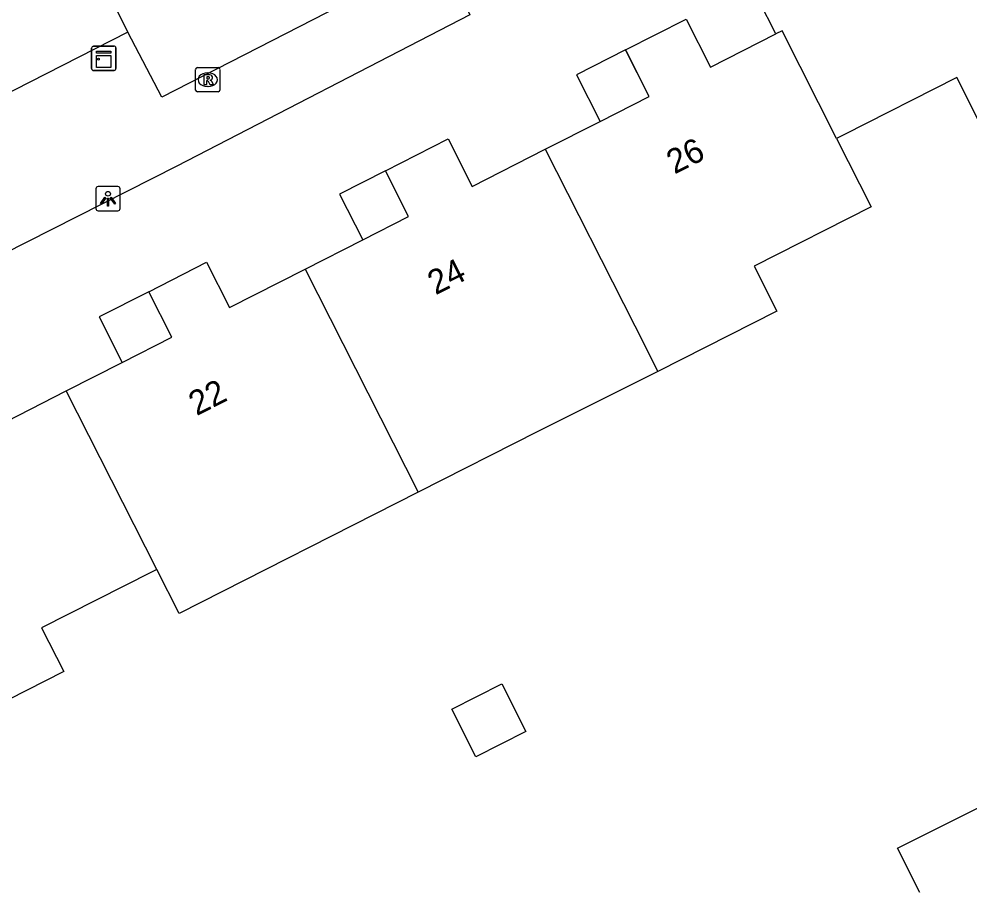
# Model space of a CAD drawing. Extents: x 162722 to 165099, y 384721 to 386283.
# Drawn here: x 163831.42 to 163870.52, y 385039.4 to 385075.21 of the extents above; entities that cross this region are included whole.
import ezdxf

# ---------------------------------------------------------------- set-up
doc = ezdxf.new("R2010")
doc.units = 0
for name, color, linetype in [('IMGEO_Kast', 7, 'Continuous'), ('IMGEO_Lichtpunt', 7, 'Continuous'), ('IMGEO_Pand', 7, 'Continuous'), ('IMGEO_Pand_nummerreeks', 7, 'Continuous'), ('IMGEO_Pand_overbouw', 7, 'Continuous'), ('IMGEO_Parkeervlak_open', 7, 'Continuous'), ('IMGEO_Rioolput', 7, 'Continuous'), ('IMGEO_Voetpad_open', 7, 'Continuous')]:
    doc.layers.add(name, color=color, linetype=linetype)

msp = doc.modelspace()

# ---------------------------------------------------------------- linework, layer by layer
at = {"layer": 'IMGEO_Kast'}
for p, q in [((163834.403, 385073.167), (163834.403, 385074.008)), ((163834.403, 385074.008), (163834.403, 385073.167)), ((163834.478, 385074.092), (163835.319, 385074.092)), ((163835.319, 385074.092), (163834.478, 385074.092)), ((163835.403, 385074.017), (163835.403, 385073.176)), ((163835.403, 385073.176), (163835.403, 385074.017)), ((163835.328, 385073.092), (163834.487, 385073.092)), ((163834.487, 385073.092), (163835.328, 385073.092))]:
    msp.add_line(p, q, dxfattribs=at)
for points in [[(163834.598, 385073.882), (163835.198, 385073.882), (163835.198, 385073.797), (163834.598, 385073.797), (163834.598, 385073.882)], [(163834.598, 385073.707), (163835.198, 385073.707), (163835.198, 385073.218), (163834.598, 385073.218), (163834.598, 385073.707)]]:
    msp.add_lwpolyline(points, dxfattribs=at)
msp.add_circle((163834.682, 385073.556), 0.0377, dxfattribs=at)
for centre, start, end in [((163834.481, 385074.014), 92.4484, 184.2845), ((163834.481, 385074.014), 92.4484, 184.2845), ((163835.325, 385074.014), 2.4484, 94.2845), ((163835.325, 385074.014), 2.4484, 94.2845), ((163834.481, 385073.17), 182.4484, 274.2845), ((163834.481, 385073.17), 182.4484, 274.2845), ((163835.325, 385073.17), 272.4484, 4.2845), ((163835.325, 385073.17), 272.4484, 4.2845)]:
    msp.add_arc(centre, 0.0779, start, end, dxfattribs=at)
at = {"layer": 'IMGEO_Lichtpunt'}
for p, q in [((163834.58, 385068.225), (163834.58, 385067.418)), ((163834.58, 385068.225), (163834.58, 385067.418)), ((163835.482, 385068.32), (163834.674, 385068.32)), ((163835.482, 385068.32), (163834.674, 385068.32)), ((163835.576, 385067.418), (163835.576, 385068.225)), ((163835.576, 385067.418), (163835.576, 385068.225)), ((163834.674, 385067.324), (163835.482, 385067.324)), ((163834.674, 385067.324), (163835.482, 385067.324))]:
    msp.add_line(p, q, dxfattribs=at)
for points in [[(163834.954, 385067.889), (163834.993, 385067.861), (163834.805, 385067.599), (163834.767, 385067.626), (163834.954, 385067.889)], [(163835.056, 385067.841), (163835.103, 385067.841), (163835.103, 385067.519), (163835.056, 385067.519), (163835.056, 385067.841)], [(163835.166, 385067.861), (163835.204, 385067.888), (163835.391, 385067.626), (163835.352, 385067.598), (163835.166, 385067.861)]]:
    msp.add_lwpolyline(points, dxfattribs=at)
msp.add_circle((163835.079, 385068.023), 0.0994, dxfattribs=at)
for centre, start, end in [((163834.674, 385068.225), 90, 180), ((163834.674, 385068.225), 90, 180), ((163835.482, 385068.225), 0, 90), ((163835.482, 385068.225), 0, 90), ((163834.674, 385067.418), 180, 270), ((163834.674, 385067.418), 180, 270), ((163835.482, 385067.418), 270, 0), ((163835.482, 385067.418), 270, 360)]:
    msp.add_arc(centre, 0.0946, start, end, dxfattribs=at)
at = {"layer": 'IMGEO_Pand'}
for points in [[(163862.538, 385074.592), (163861.139, 385077.348), (163864.257, 385078.931), (163863.307, 385080.802), (163865.619, 385081.976), (163866.538, 385080.166), (163868.8, 385081.297), (163871.258, 385082.545)], [(163853.059, 385069.852), (163855.314, 385070.997), (163857.331, 385072.021), (163856.376, 385073.904), (163856.356, 385073.944), (163858.844, 385075.207), (163859.85, 385073.227), (163862.538, 385074.592)], [(163865.034, 385070.295), (163862.792, 385074.721), (163862.538, 385074.592)], [(163875.874, 385073.435), (163870.931, 385070.924), (163869.976, 385072.803), (163865.335, 385070.447), (163865.034, 385070.295)], [(163843.179, 385064.927), (163845.555, 385066.134), (163847.437, 385067.09), (163846.484, 385068.966), (163849.067, 385070.277), (163850.057, 385068.328), (163853.059, 385069.852)], [(163865.034, 385070.295), (163866.457, 385067.487), (163861.641, 385065.042), (163862.579, 385063.193), (163857.691, 385060.711)], [(163853.059, 385069.852), (163856.741, 385062.586), (163857.691, 385060.711)], [(163833.358, 385059.919), (163835.665, 385061.09), (163837.703, 385062.124), (163836.753, 385063.996), (163839.134, 385065.205), (163840.075, 385063.351), (163843.179, 385064.927)], [(163843.179, 385064.927), (163847.83, 385055.75)], [(163857.691, 385060.711), (163852.747, 385058.247), (163847.83, 385055.75)], [(163823.548, 385054.918), (163825.861, 385056.093), (163827.851, 385057.103), (163826.898, 385058.981), (163829.459, 385060.282), (163830.405, 385058.419), (163833.358, 385059.919)], [(163837.08, 385052.574), (163833.358, 385059.919)], [(163847.83, 385055.75), (163838, 385050.758), (163837.08, 385052.574)], [(163837.08, 385052.574), (163836.867, 385052.466), (163832.345, 385050.169), (163833.255, 385048.378), (163829.454, 385046.447)], [(163852.262, 385045.918), (163850.203, 385044.873), (163849.211, 385046.826), (163851.27, 385047.872), (163852.262, 385045.918)], [(163868.454, 385039.298), (163867.535, 385041.115), (163872.606, 385043.657), (163871.554, 385045.755), (163875.979, 385047.973), (163877.043, 385045.849), (163877.48, 385046.068)]]:
    msp.add_lwpolyline(points, dxfattribs=at)
at = {"layer": 'IMGEO_Pand_overbouw'}
for points in [[(163856.356, 385073.944), (163854.339, 385072.919), (163855.314, 385070.997), (163857.331, 385072.021)], [(163846.484, 385068.966), (163844.602, 385068.01), (163845.555, 385066.134), (163847.437, 385067.09)], [(163836.753, 385063.996), (163834.715, 385062.961), (163835.665, 385061.09), (163837.703, 385062.124)]]:
    msp.add_lwpolyline(points, close=True, dxfattribs=at)
at = {"layer": 'IMGEO_Parkeervlak_open'}
for points in [[(163848.766, 385077.861), (163849.958, 385075.379), (163837.903, 385069.162), (163820.495, 385060.348), (163808.904, 385054.472)], [(163835.892, 385074.67), (163827.853, 385070.567), (163812.187, 385062.627), (163809.284, 385061.102)]]:
    msp.add_lwpolyline(points, dxfattribs=at)
at = {"layer": 'IMGEO_Rioolput'}
for p, q in [((163838.68, 385072.287), (163838.68, 385073.139)), ((163838.755, 385073.213), (163839.607, 385073.213)), ((163839.681, 385073.139), (163839.681, 385072.287)), ((163839.168, 385072.993), (163839.193, 385072.993)), ((163839.191, 385072.433), (163839.166, 385072.433)), ((163839.607, 385072.213), (163838.755, 385072.213))]:
    msp.add_line(p, q, dxfattribs=at)
for points in [[(163838.68, 385072.287), (163838.68, 385073.139)], [(163838.755, 385073.213), (163839.607, 385073.213)], [(163839.681, 385073.139), (163839.681, 385072.287)], [(163839.269, 385072.911), (163839.017, 385072.913), (163839.017, 385072.513)], [(163839.195, 385072.832), (163839.141, 385072.832), (163839.141, 385072.751)], [(163839.141, 385072.751), (163839.193, 385072.751)], [(163839.017, 385072.513), (163839.141, 385072.513), (163839.141, 385072.675), (163839.152, 385072.675)], [(163839.199, 385072.646), (163839.27, 385072.513), (163839.41, 385072.513), (163839.345, 385072.639)], [(163839.607, 385072.213), (163838.755, 385072.213)]]:
    msp.add_lwpolyline(points, dxfattribs=at)
for centre, radius, start, end in [((163838.757, 385073.137), 0.0765, 91.552, 178.448), ((163838.757, 385073.137), 0.0765, 91.552, 178.448), ((163839.605, 385073.137), 0.0765, 1.552, 88.448), ((163839.605, 385073.137), 0.0765, 1.552, 88.448), ((163839.177, 385072.94), 0.19, 274.7715, 282.9687), ((163839.201, 385072.736), 0.0964, 77.0061, 93.1865), ((163839.215, 385072.793), 0.0378, 276.6634, 79.6772), ((163839.268, 385072.801), 0.109, 350.3612, 89.416), ((163839.266, 385072.801), 0.112, 277.5842, 350.9817), ((163839.151, 385072.622), 0.0533, 26.0293, 88.6989), ((163839.25, 385072.586), 0.108, 29.5134, 73.7905), ((163838.757, 385072.289), 0.0765, 181.552, 268.448), ((163838.757, 385072.289), 0.0765, 181.552, 268.448), ((163839.605, 385072.289), 0.0765, 271.552, 358.448), ((163839.605, 385072.289), 0.0765, 271.552, 358.448)]:
    msp.add_arc(centre, radius, start, end, dxfattribs=at)
for centre, major_axis, ratio, start_param, end_param in [((163839.167, 385072.713), (-0.387, 0.002), 0.722429, 4.712389, 7.853982), ((163839.192, 385072.713), (-0.39, 0.002), 0.717154, 1.570796, 4.712389)]:
    msp.add_ellipse(centre, major_axis=major_axis, ratio=ratio, start_param=start_param, end_param=end_param, dxfattribs=at)
at = {"layer": 'IMGEO_Voetpad_open'}
for points in [[(163848.766, 385077.861), (163844.056, 385075.46), (163837.293, 385071.992), (163835.892, 385074.67)], [(163835.892, 385074.67), (163835.122, 385076.225)]]:
    msp.add_lwpolyline(points, dxfattribs=at)

# ---------------------------------------------------------------- texts
at = {"layer": 'IMGEO_Pand_nummerreeks'}
for s, p in [('26', (163858.369, 385068.81)), ('24', (163848.547, 385063.845)), ('22', (163838.722, 385058.878))]:
    msp.add_text(s, height=1, rotation=26.8202, dxfattribs=at).set_placement(p)

doc.saveas('drawing.dxf')
